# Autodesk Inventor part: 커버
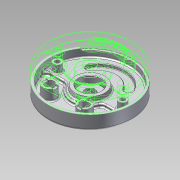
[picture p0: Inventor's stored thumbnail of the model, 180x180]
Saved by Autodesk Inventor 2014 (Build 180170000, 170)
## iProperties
Company: 한국ATC센터
Created: 2015-04
Part Number: 커버
Document SubType Name: Modeling
Designer: KYOUNG IL JANG
Density: 2.71 g/cm^3
Material: 알루미늄-6061
Mass: 1067.8 g
Surface Area: 1019.64 cm^2
Volume: 394.022 cm^3
Appearance: 매끄러움 - 흰색
Author: KYOUNG IL JANG
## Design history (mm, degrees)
sketch "스케치1"
  geometry: L1 (-59, -19)-(-59, 19); L2 (59, 19)-(59, -19); L3 (-41, 19)-(-41, -19); L4 (41, -19)-(41, 19); L5 (38.527, 33.023)-(55.442, 39.179); L6 (-38.527, 33.023)-(-55.442, 39.179); C1 r 90 at (0, 0); C2 r 95 at (0, 0); A1 r 59 centre (0, 19) between (59, 19) and (-59, 19); A2 r 59 centre (0, -19) between (-59, -19) and (59, -19); A3 r 41 centre (0, -19) between (-41, -19) and (41, -19); A4 r 41 centre (0, 19) between (41, 19) and (-41, 19); 2 further points
  constraints: 12 end point, 12 point on circle, 6 centre point, 4 tangent, 2 parallel, 2 point on line, 1 coincident, 1 horizontal alignment, 1 midpoint, 1 vertical, 1 vertical alignment, 3 other
  dimensions: "d2" = 180 diameter of C1; "d3" = 156 dimension on A2 A1; "d4" = 118 distance between parallel lines of L2 L1; "d5" = 18 distance between parallel lines of L2 L4; "d8" = 190 diameter of C2; "d120" = 140 deg angle of L6 L5; "d121" = 110 deg dimension on A1.centre point (0, 0) L5.end
extrude "돌출1" new body sketch "스케치1" distance "d6" = 14; taper "d7" = 0 deg
extrude "돌출2" join sketch "스케치1" distance "d9" = 13; taper "d10" = 0 deg
extrude "돌출3" cut sketch "스케치1" distance "d11" = 7; taper "d12" = 0 deg
sketch "스케치2"
  geometry: C1 r 11.5 at (0, 0); 1 further point
  constraints: 1 centre point, 1 coincident
  dimensions: "d13" = 23 diameter of C1
extrude "돌출4" cut sketch "스케치2" stored distance "d14" = 7; taper "d15" = 0 deg
fillet "모깎기1"
fillet "모깎기2"
sketch "스케치3"
  geometry: L1 (-73.724, 51.622)-(-77.819, 54.49); L2 (73.724, 51.622)-(77.819, 54.49); L3 (0, 0)-(0, -90); A1 r 95 centre (0, 0) between (-77.819, 54.49) and (77.819, 54.49) reference; A2 r 90 centre (0, 0) between (-73.724, 51.622) and (73.724, 51.622) reference; 1 further point
  constraints: 6 end point, 5 point on circle, 1 point on line, 1 vertical, 1 other
  dimensions: "d16" = 250 deg dimension on L2 L1
extrude "돌출5" join sketch "스케치3" distance "d17" = 5; taper "d18" = 0 deg
hole "구멍1" diameter "d21" = 50; stored, may be unused: countersink angle "d25" = 90 deg, drill point angle "d27" = 0 deg; dims "d19" = 10, "d20" = 10, "d22" = 6, "d23" = 4, "d24" = 2, "d26" = 5
fillet "모깎기3" dims "d28" = 0.3
fillet "모깎기5" dims "d30" = 3
sketch "스케치4"
  geometry: C1 r 35 at (0, 0); C2 r 25 at (0, 0); 1 further point
  constraints: 2 centre point, 1 coincident
  dimensions: "d32" = 70 diameter of C1 (derived); "d36" = 10 radial gap between concentric circles of C1 C2
extrude "돌출6" join sketch "스케치4" distance "d33" = 10; taper "d34" = 0 deg
feature "면 기울기2" dims angle "d37" = 10 deg
chamfer "모따기1" distance "d39" = 1; stored, may be unused: second distance "d40" = 2, angle "d41" = 45 deg
fillet "모깎기7" dims "d42" = 5
sketch "스케치5"
  geometry: L1 (-40.249, -12)-(-89.196, -12); L2 (40.249, -12)-(89.196, -12); A1 r 90 centre (0, 0) between (-89.196, -12) and (89.196, -12) reference; A2 r 42 centre (0, 0) between (-40.249, -12) and (40.249, -12); 1 further point
  constraints: 4 end point, 4 point on circle, 1 centre point, 1 collinear, 1 horizontal, 1 point on line
  dimensions: "d43" = 48 radial gap between concentric circles of A1 A2; "d44" = 12 distance from line of point (0, 0) L1
extrude "돌출7" cut sketch "스케치5" stored distance "d45" = 10; taper "d46" = 0 deg
fillet "모깎기8" dims "d47" = 10
chamfer "모따기2" distance "d49" = 1; stored, may be unused: second distance "d50" = 2, angle "d51" = 45 deg
sketch "스케치7"
  geometry: L1 (36.062, 36.062)-(50.912, 50.912); L2 (-36.062, 36.062)-(-50.912, 50.912); A1 r 72 centre (0, 0) between (50.912, 50.912) and (-50.912, 50.912); A2 r 51 centre (0, 0) between (36.062, 36.062) and (-36.062, 36.062); 1 further point
  constraints: 8 point on circle, 4 end point, 2 centre point, 2 point on line, 1 coincident, 1 horizontal alignment
  dimensions: "d54" = 72 radius of A1; "d55" = 21 radial gap between concentric circles of A1 A2; "d56" = 90 deg angle of L2 L1
extrude "돌출8" join sketch "스케치7" distance "d57" = 5; taper "d58" = 0 deg
fillet "모깎기10" dims "d59" = 5
fillet "모깎기11" dims "d60" = 5
fillet "모깎기12" dims "d61" = 3
sketch "스케치6"
  geometry: C1 r 68 at (0, 0); 1 further point
  constraints: 1 centre point, 1 other
  dimensions: "d119" = 136 diameter of C1
feature "엠보싱1" sketch "스케치6" dims "d62" = 0.5, "d63" = 0
sketch "스케치8"
  geometry: C1 r 9 at (74, 0); C2 r 9 at (-74, 0); A1 r 74 centre (0, 0) between (74, 0) and (-74, 0); 1 further point
  constraints: 3 centre point, 2 horizontal alignment, 2 point on circle, 1 coincident, 1 equal radius
  dimensions: "d64" = 18 diameter of C1; "d65" = 148 diameter of A1
extrude "돌출9" join sketch "스케치8" stored distance "d66" = 5; taper "d67" = 0 deg
sketch "스케치11"
  geometry: C1 r 15 at (40, -52); C2 r 15 at (-40, -52); 1 further point
  constraints: 2 centre point, 1 equal radius, 1 horizontal alignment
  dimensions: "d83" = 52 vertical distance of point (0, 0) C1.centre; "d84" = 80 distance of C2.centre C1.centre; "d85" = 40 horizontal distance of point (0, 0) C1.centre (= 0.5 x d84); "d86" = 30 diameter of C1
extrude "돌출10" join sketch "스케치11" stored distance "d87" = 5; taper "d88" = 0 deg
node "구멍3"
node "구멍5"
hole "구멍6" diameter "d93" = 20; stored, may be unused: countersink angle "d97" = 90 deg, drill point angle "d99" = 118 deg; dims "d91" = 10, "d92" = 10, "d94" = 6, "d95" = 4, "d96" = 2, "d98" = 8
hole "구멍7" diameter "d102" = 20; stored, may be unused: countersink angle "d106" = 90 deg, drill point angle "d108" = 118 deg; dims "d100" = 10, "d101" = 10, "d103" = 6, "d104" = 4, "d105" = 2, "d107" = 8
sketch "스케치13"
  geometry: L1 (6, -13.748)-(6, -8); L2 (6, 8)-(6, 13.748); L3 (-6, -13.748)-(-6, -8); L4 (-6, 8)-(-6, 13.748); L5 (-66.252, -6)-(-72, -6); L6 (-88, -6)-(-93.748, -6); L7 (-66.252, 6)-(-72, 6); L8 (-88, 6)-(-93.748, 6); A1 r 15 centre (0, 0) between (6, -13.748) and (6, 13.748) reference; A2 r 10 centre (0, 0) between (6, -8) and (6, 8) reference; A3 r 15 centre (-80, 0) between (-66.252, -6) and (-93.748, -6) reference; A4 r 10 centre (-80, 0) between (-72, -6) and (-88, -6) reference; 1 further point
  constraints: 16 end point, 16 point on circle, 4 equal length, 3 collinear, 2 point on line, 1 perpendicular, 1 vertical
  dimensions: "d109" = 12 distance between parallel lines of L3 L1; "d110" = 6 distance from line of A1.centre L1 (= 0.5 x d109); "d111" = 12 distance between parallel lines of L7 L5; "d112" = 6 distance from line of A3.centre L5 (= 0.5 x d111)
extrude "돌출12" cut sketch "스케치13" distance "d113" = 3; taper "d114" = 0 deg
fillet "모깎기13" dims "d115" = 3
fillet "모깎기14" dims "d116" = 1
node "솔리드1"
sketch "스케치9"
  geometry: 1 further point
hole "구멍2" sketch "스케치9" diameter "d68" = 11; stored, may be unused: countersink angle "d72" = 90 deg, drill point angle "d74" = 0 deg; dims "d69" = 6, "d70" = 18, "d71" = 11, "d73" = 8
sketch "스케치10"
  geometry: 1 further point
hole "구멍4" sketch "스케치10" diameter "d75" = 11; stored, may be unused: countersink angle "d79" = 90 deg, drill point angle "d81" = 0 deg; dims "d76" = 6, "d77" = 18, "d78" = 11, "d80" = 8
